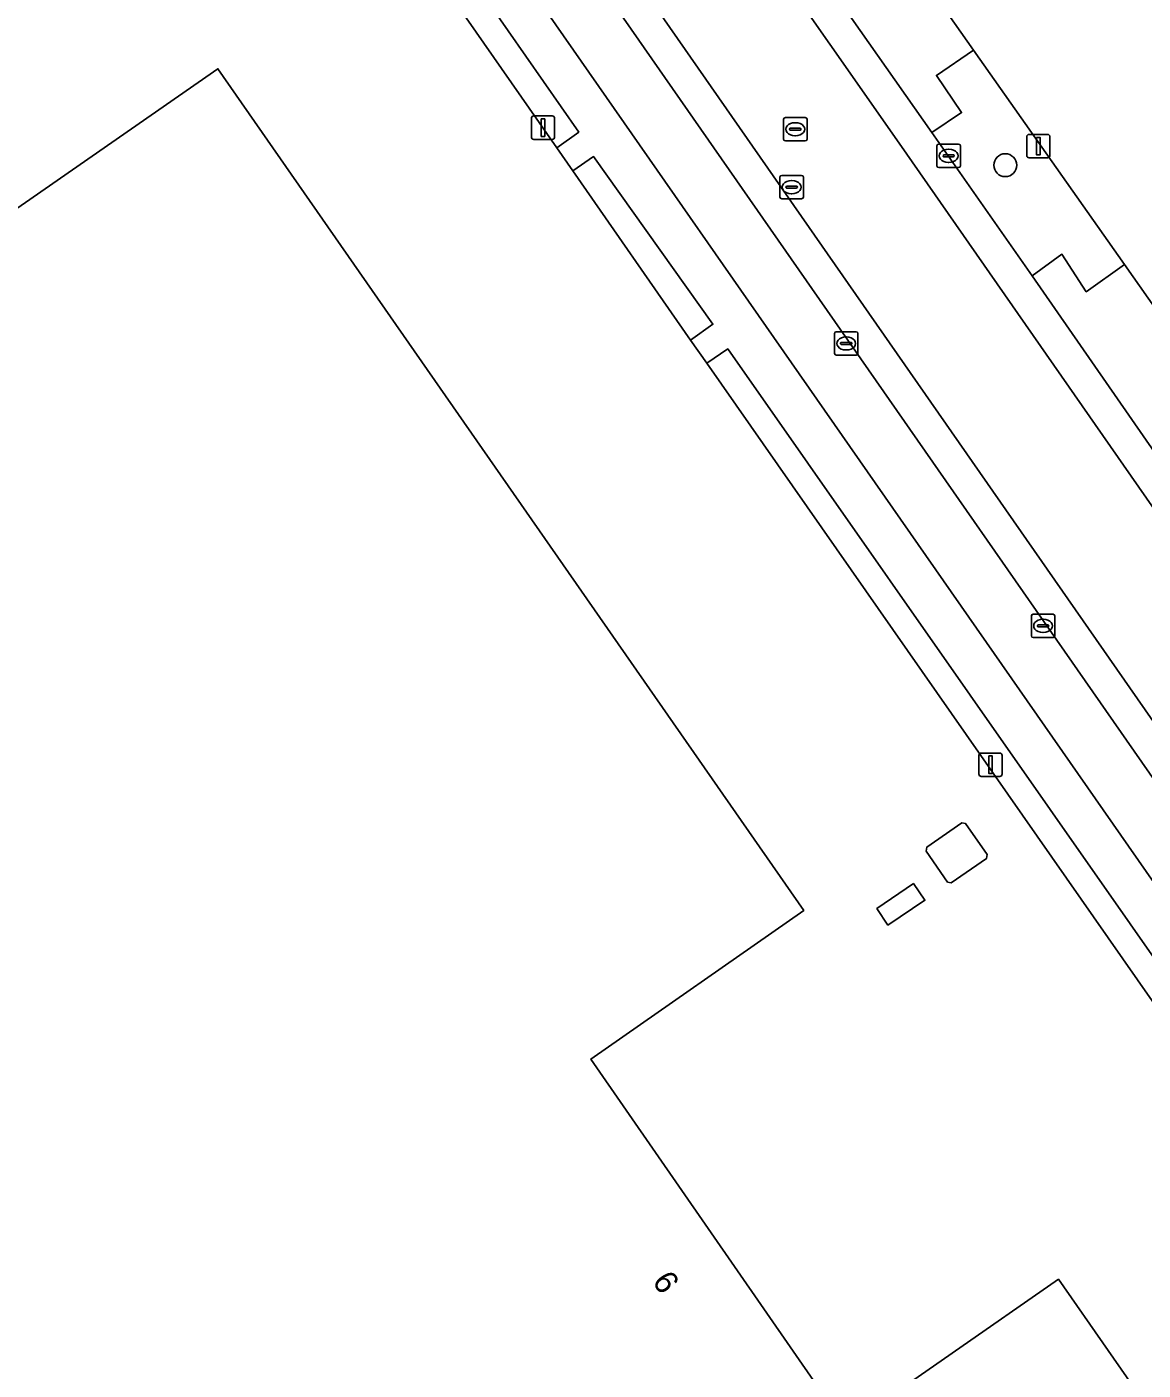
# Model space of a CAD drawing. Extents: x 156702 to 158052, y 387630 to 388992.
# Drawn here: x 157213.5 to 157261.2, y 388126 to 388183.4 of the extents above; entities that cross this region are included whole.
import ezdxf

# ---------------------------------------------------------------- set-up
doc = ezdxf.new("R2010")
doc.units = 0
for name, color, linetype in [('IMGEO_Berm_groen', 7, 'Continuous'), ('IMGEO_Boom', 7, 'Continuous'), ('IMGEO_Erf', 7, 'Continuous'), ('IMGEO_Groenvoorziening', 7, 'Continuous'), ('IMGEO_Kolk', 7, 'Continuous'), ('IMGEO_Lage_trafo', 7, 'Continuous'), ('IMGEO_Lichtmast', 7, 'Continuous'), ('IMGEO_Pand', 7, 'Continuous'), ('IMGEO_Pand_nummerreeks', 7, 'Continuous'), ('IMGEO_Parkeervlak_open', 7, 'Continuous'), ('IMGEO_Rijbaan_lokaal_gesloten', 7, 'Continuous'), ('IMGEO_Rijbaan_lokaal_open', 7, 'Continuous'), ('IMGEO_Rioolput', 7, 'Continuous'), ('IMGEO_Verkeersbordpaal', 7, 'Continuous'), ('IMGEO_Voetpad_open', 7, 'Continuous')]:
    doc.layers.add(name, color=color, linetype=linetype)

msp = doc.modelspace()

# ---------------------------------------------------------------- linework, layer by layer
at = {"layer": 'IMGEO_Berm_groen'}
msp.add_lwpolyline([(157253.951, 388182.374), (157252.369, 388181.296), (157253.443, 388179.711), (157252.169, 388178.864), (157256.455, 388172.746), (157257.73, 388173.658), (157258.77, 388172.059), (157260.401, 388173.229)], close=True, dxfattribs=at)
at = {"layer": 'IMGEO_Boom'}
msp.add_circle((157255.309, 388177.463), 0.489, dxfattribs=at)
at = {"layer": 'IMGEO_Erf'}
for points in [[(157171.132, 388300.752), (157172.367, 388299.009), (157193.882, 388268.245), (157194.975, 388266.682), (157200.032, 388259.496), (157200.786, 388258.42), (157207.925, 388248.229), (157212.342, 388241.924), (157218.512, 388233.115), (157232.439, 388213.235), (157238.976, 388203.904), (157243.285, 388197.598), (157250.344, 388187.533), (157253.951, 388182.374), (157260.401, 388173.229), (157265.086, 388166.567), (157269.88, 388159.622), (157271.116, 388157.832), (157273.661, 388154.215), (157277.716, 388148.352), (157281.526, 388142.848), (157289.3, 388131.616), (157294.457, 388124.387)], [(157242.574, 388169.007), (157241.87, 388169.99), (157236.847, 388177.226), (157236.169, 388178.201), (157228.416, 388189.316), (157222.314, 388197.962), (157192.467, 388240.777), (157190.75, 388243.22), (157186.236, 388249.801), (157179.863, 388258.901), (157178.825, 388260.626), (157177.984, 388261.818), (157175.156, 388265.898), (157173.142, 388268.766), (157170.643, 388272.326), (157156.349, 388292.803), (157153.912, 388296.208)], [(157275.556, 388121.786), (157271.06, 388128.215), (157265.86, 388135.653), (157242.574, 388169.007)]]:
    msp.add_lwpolyline(points, dxfattribs=at)
for points in [[(157161.84, 388143.245), (157208.169, 388175.506), (157211.076, 388177.53), (157212.642, 388175.281), (157221.693, 388181.584), (157246.706, 388145.644), (157237.62, 388139.301), (157239.125, 388137.125), (157248.5, 388123.588), (157257.578, 388129.897), (157272.425, 388108.581), (157214.226, 388068.097), (157199.722, 388088.956), (157189.962, 388102.891)], [(157253.449, 388149.387), (157253.618, 388149.352), (157254.541, 388148.028), (157254.503, 388147.862), (157253.006, 388146.829), (157252.847, 388146.859), (157251.929, 388148.177), (157251.962, 388148.352)], [(157249.828, 388145.725), (157251.391, 388146.79), (157251.877, 388146.083), (157250.299, 388145.017)]]:
    msp.add_lwpolyline(points, close=True, dxfattribs=at)
at = {"layer": 'IMGEO_Groenvoorziening'}
for points in [[(157236.169, 388178.201), (157237.097, 388178.88), (157230.32, 388188.624), (157229.362, 388189.981), (157228.416, 388189.316)], [(157241.87, 388169.99), (157242.83, 388170.675), (157237.731, 388177.828), (157236.847, 388177.226)], [(157270.989, 388130.287), (157243.463, 388169.622), (157242.574, 388169.007), (157265.86, 388135.653), (157271.06, 388128.215), (157272.006, 388128.857)]]:
    msp.add_lwpolyline(points, close=True, dxfattribs=at)
at = {"layer": 'IMGEO_Kolk'}
for p, q in [((157252.393, 388177.436), (157252.393, 388178.288)), ((157252.468, 388178.362), (157253.32, 388178.362)), ((157252.881, 388178.142), (157252.906, 388178.142)), ((157253.394, 388178.288), (157253.394, 388177.436)), ((157252.652, 388177.856), (157252.652, 388177.868)), ((157253.09, 388177.819), (157252.692, 388177.819)), ((157252.695, 388177.905), (157253.093, 388177.905)), ((157252.904, 388177.582), (157252.879, 388177.582)), ((157253.136, 388177.868), (157253.136, 388177.856)), ((157253.32, 388177.362), (157252.468, 388177.362)), ((157248.018, 388169.428), (157248.018, 388170.28)), ((157248.093, 388170.354), (157248.945, 388170.354)), ((157248.506, 388170.134), (157248.531, 388170.134)), ((157249.019, 388170.28), (157249.019, 388169.428)), ((157248.277, 388169.848), (157248.277, 388169.86)), ((157248.715, 388169.811), (157248.317, 388169.811)), ((157248.32, 388169.897), (157248.718, 388169.897)), ((157248.529, 388169.574), (157248.504, 388169.574)), ((157248.761, 388169.86), (157248.761, 388169.848)), ((157248.945, 388169.354), (157248.093, 388169.354)), ((157256.423, 388157.369), (157256.423, 388158.221)), ((157256.498, 388158.295), (157257.35, 388158.295)), ((157256.911, 388158.075), (157256.936, 388158.075)), ((157257.424, 388158.221), (157257.424, 388157.369)), ((157256.682, 388157.789), (157256.682, 388157.801)), ((157257.12, 388157.752), (157256.722, 388157.752)), ((157256.725, 388157.838), (157257.123, 388157.838)), ((157256.934, 388157.515), (157256.909, 388157.515)), ((157257.166, 388157.801), (157257.166, 388157.789)), ((157257.35, 388157.295), (157256.498, 388157.295))]:
    msp.add_line(p, q, dxfattribs=at)
for points in [[(157252.393, 388177.436), (157252.393, 388178.288)], [(157252.468, 388178.362), (157253.32, 388178.362)], [(157253.394, 388178.288), (157253.394, 388177.436)], [(157253.32, 388177.362), (157252.468, 388177.362)], [(157248.018, 388169.428), (157248.018, 388170.28)], [(157248.093, 388170.354), (157248.945, 388170.354)], [(157249.019, 388170.28), (157249.019, 388169.428)], [(157248.945, 388169.354), (157248.093, 388169.354)], [(157256.423, 388157.369), (157256.423, 388158.221)], [(157256.498, 388158.295), (157257.35, 388158.295)], [(157257.424, 388158.221), (157257.424, 388157.369)], [(157257.35, 388157.295), (157256.498, 388157.295)]]:
    msp.add_lwpolyline(points, dxfattribs=at)
for centre, radius, start, end in [((157252.47, 388178.286), 0.0765, 91.55205, 178.44795), ((157252.47, 388178.286), 0.0765, 91.55205, 178.44795), ((157253.318, 388178.286), 0.0765, 1.55205, 88.44795), ((157253.318, 388178.286), 0.0765, 1.55205, 88.44795), ((157252.692, 388177.865), 0.0403, 85.87752, 175.75265), ((157252.689, 388177.855), 0.0366, 178.93798, 274.71019), ((157253.093, 388177.862), 0.043, 264.86636, 352.45326), ((157253.097, 388177.867), 0.0386, 1.73085, 96.63898), ((157252.47, 388177.438), 0.0765, 181.55205, 268.44795), ((157252.47, 388177.438), 0.0765, 181.55205, 268.44795), ((157253.318, 388177.438), 0.0765, 271.55205, 358.44795), ((157253.318, 388177.438), 0.0765, 271.55205, 358.44795), ((157248.095, 388170.278), 0.0765, 91.55205, 178.44795), ((157248.095, 388170.278), 0.0765, 91.55205, 178.44795), ((157248.943, 388170.278), 0.0765, 1.55205, 88.44795), ((157248.943, 388170.278), 0.0765, 1.55205, 88.44795), ((157248.317, 388169.857), 0.0403, 85.87752, 175.75265), ((157248.314, 388169.847), 0.0366, 178.93798, 274.71019), ((157248.718, 388169.854), 0.043, 264.86636, 352.45326), ((157248.722, 388169.859), 0.0386, 1.73085, 96.63898), ((157248.095, 388169.43), 0.0765, 181.55205, 268.44795), ((157248.095, 388169.43), 0.0765, 181.55205, 268.44795), ((157248.943, 388169.43), 0.0765, 271.55205, 358.44795), ((157248.943, 388169.43), 0.0765, 271.55205, 358.44795), ((157256.5, 388158.219), 0.0765, 91.55205, 178.44795), ((157256.5, 388158.219), 0.0765, 91.55205, 178.44795), ((157257.348, 388158.219), 0.0765, 1.55205, 88.44795), ((157257.348, 388158.219), 0.0765, 1.55205, 88.44795), ((157256.722, 388157.798), 0.0403, 85.87752, 175.75265), ((157256.719, 388157.788), 0.0366, 178.93798, 274.71019), ((157257.123, 388157.795), 0.043, 264.86636, 352.45326), ((157257.127, 388157.8), 0.0386, 1.73085, 96.63898), ((157256.5, 388157.371), 0.0765, 181.55205, 268.44795), ((157256.5, 388157.371), 0.0765, 181.55205, 268.44795), ((157257.348, 388157.371), 0.0765, 271.55205, 358.44795), ((157257.348, 388157.371), 0.0765, 271.55205, 358.44795)]:
    msp.add_arc(centre, radius, start, end, dxfattribs=at)
for centre, major_axis, ratio, start_param, end_param in [((157252.88, 388177.862), (-0.387, 0.002), 0.722429, 4.712389, 7.853982), ((157252.905, 388177.862), (-0.39, 0.002), 0.717154, 1.570796, 4.712389), ((157248.505, 388169.854), (-0.387, 0.002), 0.722429, 4.712389, 7.853982), ((157248.53, 388169.854), (-0.39, 0.002), 0.717154, 1.570796, 4.712389), ((157256.91, 388157.795), (-0.387, 0.002), 0.722429, 4.712389, 7.853982), ((157256.935, 388157.795), (-0.39, 0.002), 0.717154, 1.570796, 4.712389)]:
    msp.add_ellipse(centre, major_axis=major_axis, ratio=ratio, start_param=start_param, end_param=end_param, dxfattribs=at)
at = {"layer": 'IMGEO_Lage_trafo'}
for points in [[(157253.006, 388146.829), (157254.503, 388147.862), (157254.541, 388148.028), (157253.618, 388149.352), (157253.449, 388149.387), (157251.962, 388148.352), (157251.929, 388148.177), (157252.847, 388146.859)], [(157250.299, 388145.017), (157251.877, 388146.083), (157251.391, 388146.79), (157249.828, 388145.725)]]:
    msp.add_lwpolyline(points, close=True, dxfattribs=at)
at = {"layer": 'IMGEO_Lichtmast'}
for p, q in [((157235.079, 388178.665), (157235.079, 388179.465)), ((157235.079, 388179.465), (157235.079, 388178.665)), ((157235.179, 388179.565), (157235.969, 388179.565)), ((157235.969, 388179.565), (157235.179, 388179.565)), ((157236.069, 388179.465), (157236.069, 388178.665)), ((157236.069, 388178.665), (157236.069, 388179.465)), ((157235.969, 388178.565), (157235.179, 388178.565)), ((157235.179, 388178.565), (157235.969, 388178.565)), ((157254.285, 388152.367), (157255.075, 388152.367)), ((157255.075, 388152.367), (157254.285, 388152.367)), ((157254.185, 388151.467), (157254.185, 388152.267)), ((157254.185, 388152.267), (157254.185, 388151.467)), ((157255.175, 388152.267), (157255.175, 388151.467)), ((157255.175, 388151.467), (157255.175, 388152.267)), ((157255.075, 388151.367), (157254.285, 388151.367)), ((157254.285, 388151.367), (157255.075, 388151.367))]:
    msp.add_line(p, q, dxfattribs=at)
for points in [[(157235.499, 388179.44), (157235.649, 388179.44), (157235.649, 388178.69), (157235.499, 388178.69), (157235.499, 388179.44)], [(157254.605, 388152.242), (157254.755, 388152.242), (157254.755, 388151.492), (157254.605, 388151.492), (157254.605, 388152.242)]]:
    msp.add_lwpolyline(points, dxfattribs=at)
for centre, start, end in [((157235.179, 388179.465), 90, 180), ((157235.179, 388179.465), 90, 180), ((157235.969, 388179.465), 0, 90), ((157235.969, 388179.465), 360, 90), ((157235.179, 388178.665), 180, 270), ((157235.179, 388178.665), 180, 270), ((157235.969, 388178.665), 270, 0), ((157235.969, 388178.665), 270, 0), ((157254.285, 388152.267), 90, 180), ((157254.285, 388152.267), 90, 180), ((157255.075, 388152.267), 0, 90), ((157255.075, 388152.267), 360, 90), ((157254.285, 388151.467), 180, 270), ((157254.285, 388151.467), 180, 270), ((157255.075, 388151.467), 270, 0), ((157255.075, 388151.467), 270, 0)]:
    msp.add_arc(centre, 0.1, start, end, dxfattribs=at)
at = {"layer": 'IMGEO_Pand'}
msp.add_lwpolyline([(157257.578, 388129.897), (157248.5, 388123.588), (157239.125, 388137.125), (157237.62, 388139.301), (157246.706, 388145.644), (157221.693, 388181.584), (157212.642, 388175.281), (157211.076, 388177.53), (157208.169, 388175.506), (157161.84, 388143.245), (157189.962, 388102.891), (157199.722, 388088.956), (157214.226, 388068.097), (157272.425, 388108.581)], close=True, dxfattribs=at)
at = {"layer": 'IMGEO_Parkeervlak_open'}
msp.add_lwpolyline([(157236.036, 388188.018), (157233.871, 388191.118), (157231.797, 388189.67), (157272.471, 388131.321), (157272.551, 388131.207), (157274.579, 388132.691)], close=True, dxfattribs=at)
at = {"layer": 'IMGEO_Rijbaan_lokaal_gesloten'}
for points in [[(157290.068, 388122.059), (157284.128, 388130.537), (157250.785, 388178.4), (157218.017, 388225.194), (157168.536, 388296.106), (157166.328, 388299.54), (157165.346, 388302.72), (157165.232, 388304.849), (157165.572, 388307.171), (157166.44, 388309.461), (157166.862, 388310.136), (157167.285, 388310.812), (157167.449, 388311.074), (157168.134, 388311.902), (157169.086, 388312.83), (157170.115, 388313.613), (157170.159, 388313.64), (157171.244, 388314.319), (157146.447, 388301.446), (157146.433, 388301.427)], [(157170.823, 388312.404), (157166.862, 388310.136), (157166.44, 388309.461), (157165.572, 388307.171), (157165.232, 388304.849), (157165.346, 388302.72), (157166.328, 388299.54), (157168.536, 388296.106), (157218.017, 388225.194), (157250.785, 388178.4), (157284.128, 388130.537), (157290.068, 388122.059)], [(157159.256, 388297.816), (157160.307, 388298.772), (157166.301, 388290.299), (157236.347, 388190.018), (157288.771, 388114.767), (157287.657, 388113.917), (157306.474, 388095.88), (157307.404, 388097.063), (157338.534, 388071.878), (157341.899, 388076.038), (157340.456, 388076.982), (157309.901, 388101.717)], [(157293.74, 388119.458), (157291.999, 388121.743), (157285.376, 388131.195), (157279.247, 388139.992), (157275.903, 388144.791), (157269.683, 388153.769), (157268.767, 388155.125), (157267.467, 388156.891), (157263.265, 388162.929), (157256.455, 388172.746), (157252.169, 388178.864), (157246.429, 388187.061), (157241.532, 388194.055), (157234.617, 388203.884), (157230.6, 388209.644), (157214.539, 388232.609), (157210.521, 388238.352), (157203.933, 388247.771), (157199.027, 388254.836), (157191.042, 388266.266), (157169.573, 388297.067), (157168.386, 388298.814)]]:
    msp.add_lwpolyline(points, dxfattribs=at)
msp.add_lwpolyline([(157166.301, 388290.299), (157160.307, 388298.772), (157159.256, 388297.816), (157162.309, 388293.557), (157162.638, 388293.099), (157174.157, 388276.608), (157180.506, 388267.519), (157183.303, 388263.514), (157191.992, 388251.074), (157225.926, 388202.493), (157233.871, 388191.118), (157236.036, 388188.018), (157274.579, 388132.691), (157280.876, 388123.651), (157287.657, 388113.917), (157288.771, 388114.767), (157236.347, 388190.018)], close=True, dxfattribs=at)
at = {"layer": 'IMGEO_Rijbaan_lokaal_open'}
for points in [[(157252.169, 388178.864), (157253.443, 388179.711), (157252.369, 388181.296), (157253.951, 388182.374), (157250.344, 388187.533), (157248.791, 388186.418), (157247.671, 388187.969), (157246.429, 388187.061)], [(157263.265, 388162.929), (157264.54, 388163.836), (157263.445, 388165.387), (157265.086, 388166.567), (157260.401, 388173.229), (157258.77, 388172.059), (157257.73, 388173.658), (157256.455, 388172.746)]]:
    msp.add_lwpolyline(points, close=True, dxfattribs=at)
at = {"layer": 'IMGEO_Rioolput'}
for p, q in [((157245.845, 388178.571), (157245.845, 388179.423)), ((157245.92, 388179.497), (157246.772, 388179.497)), ((157246.846, 388179.423), (157246.846, 388178.571)), ((157246.104, 388178.991), (157246.104, 388179.003)), ((157246.542, 388178.954), (157246.144, 388178.954)), ((157246.147, 388179.04), (157246.545, 388179.04)), ((157246.356, 388178.717), (157246.331, 388178.717)), ((157246.333, 388179.277), (157246.358, 388179.277)), ((157246.588, 388179.003), (157246.588, 388178.991)), ((157246.772, 388178.497), (157245.92, 388178.497)), ((157245.764, 388177.027), (157246.616, 388177.027)), ((157245.689, 388176.101), (157245.689, 388176.953)), ((157245.948, 388176.521), (157245.948, 388176.533)), ((157246.386, 388176.484), (157245.988, 388176.484)), ((157245.991, 388176.57), (157246.389, 388176.57)), ((157246.177, 388176.807), (157246.202, 388176.807)), ((157246.432, 388176.533), (157246.432, 388176.521)), ((157246.69, 388176.953), (157246.69, 388176.101)), ((157246.616, 388176.027), (157245.764, 388176.027)), ((157246.2, 388176.247), (157246.175, 388176.247))]:
    msp.add_line(p, q, dxfattribs=at)
for points in [[(157245.845, 388178.571), (157245.845, 388179.423)], [(157245.92, 388179.497), (157246.772, 388179.497)], [(157246.846, 388179.423), (157246.846, 388178.571)], [(157246.772, 388178.497), (157245.92, 388178.497)], [(157245.764, 388177.027), (157246.616, 388177.027)], [(157245.689, 388176.101), (157245.689, 388176.953)], [(157246.69, 388176.953), (157246.69, 388176.101)], [(157246.616, 388176.027), (157245.764, 388176.027)]]:
    msp.add_lwpolyline(points, dxfattribs=at)
for centre, radius, start, end in [((157245.922, 388179.421), 0.0765, 91.55205, 178.44795), ((157245.922, 388179.421), 0.0765, 91.55205, 178.44795), ((157246.77, 388179.421), 0.0765, 1.55205, 88.44795), ((157246.77, 388179.421), 0.0765, 1.55205, 88.44795), ((157246.144, 388179), 0.0403, 85.87752, 175.75265), ((157246.141, 388178.99), 0.0366, 178.93798, 274.71019), ((157246.545, 388178.997), 0.043, 264.86636, 352.45326), ((157246.549, 388179.002), 0.0386, 1.73085, 96.63898), ((157245.922, 388178.573), 0.0765, 181.55205, 268.44795), ((157245.922, 388178.573), 0.0765, 181.55205, 268.44795), ((157246.77, 388178.573), 0.0765, 271.55205, 358.44795), ((157246.77, 388178.573), 0.0765, 271.55205, 358.44795), ((157245.766, 388176.951), 0.0765, 91.55205, 178.44795), ((157245.766, 388176.951), 0.0765, 91.55205, 178.44795), ((157246.614, 388176.951), 0.0765, 1.55205, 88.44795), ((157246.614, 388176.951), 0.0765, 1.55205, 88.44795), ((157245.988, 388176.53), 0.0403, 85.87752, 175.75265), ((157245.985, 388176.52), 0.0366, 178.93798, 274.71019), ((157246.389, 388176.527), 0.043, 264.86636, 352.45326), ((157246.393, 388176.532), 0.0386, 1.73085, 96.63898), ((157245.766, 388176.103), 0.0765, 181.55205, 268.44795), ((157245.766, 388176.103), 0.0765, 181.55205, 268.44795), ((157246.614, 388176.103), 0.0765, 271.55205, 358.44795), ((157246.614, 388176.103), 0.0765, 271.55205, 358.44795)]:
    msp.add_arc(centre, radius, start, end, dxfattribs=at)
for centre, major_axis, ratio, start_param, end_param in [((157246.332, 388178.997), (-0.387, 0.002), 0.722429, 4.712389, 7.853982), ((157246.357, 388178.997), (-0.39, 0.002), 0.717154, 1.570796, 4.712389), ((157246.176, 388176.527), (-0.387, 0.002), 0.722429, 4.712389, 7.853982), ((157246.201, 388176.527), (-0.39, 0.002), 0.717154, 1.570796, 4.712389)]:
    msp.add_ellipse(centre, major_axis=major_axis, ratio=ratio, start_param=start_param, end_param=end_param, dxfattribs=at)
at = {"layer": 'IMGEO_Verkeersbordpaal'}
for p, q in [((157256.327, 388178.777), (157257.117, 388178.777)), ((157257.117, 388178.777), (157256.327, 388178.777)), ((157256.227, 388177.877), (157256.227, 388178.677)), ((157256.227, 388178.677), (157256.227, 388177.877)), ((157257.217, 388178.677), (157257.217, 388177.877)), ((157257.217, 388177.877), (157257.217, 388178.677)), ((157257.117, 388177.777), (157256.327, 388177.777)), ((157256.327, 388177.777), (157257.117, 388177.777))]:
    msp.add_line(p, q, dxfattribs=at)
msp.add_lwpolyline([(157256.647, 388178.652), (157256.797, 388178.652), (157256.797, 388177.902), (157256.647, 388177.902), (157256.647, 388178.652)], dxfattribs=at)
for centre, start, end in [((157256.327, 388178.677), 90, 180), ((157256.327, 388178.677), 90, 180), ((157257.117, 388178.677), 0, 90), ((157257.117, 388178.677), 360, 90), ((157256.327, 388177.877), 180, 270), ((157256.327, 388177.877), 180, 270), ((157257.117, 388177.877), 270, 0), ((157257.117, 388177.877), 270, 0)]:
    msp.add_arc(centre, 0.1, start, end, dxfattribs=at)
at = {"layer": 'IMGEO_Voetpad_open'}
msp.add_lwpolyline([(157272.471, 388131.321), (157231.797, 388189.67), (157230.32, 388188.624), (157237.097, 388178.88), (157236.169, 388178.201), (157236.847, 388177.226), (157237.731, 388177.828), (157242.83, 388170.675), (157241.87, 388169.99), (157242.574, 388169.007), (157243.463, 388169.622), (157270.989, 388130.287)], close=True, dxfattribs=at)

# ---------------------------------------------------------------- texts
at = {"layer": 'IMGEO_Pand_nummerreeks'}
msp.add_text('6', height=1, rotation=304.69951, dxfattribs=at).set_placement((157240.207, 388129.804))

doc.saveas('drawing.dxf')
